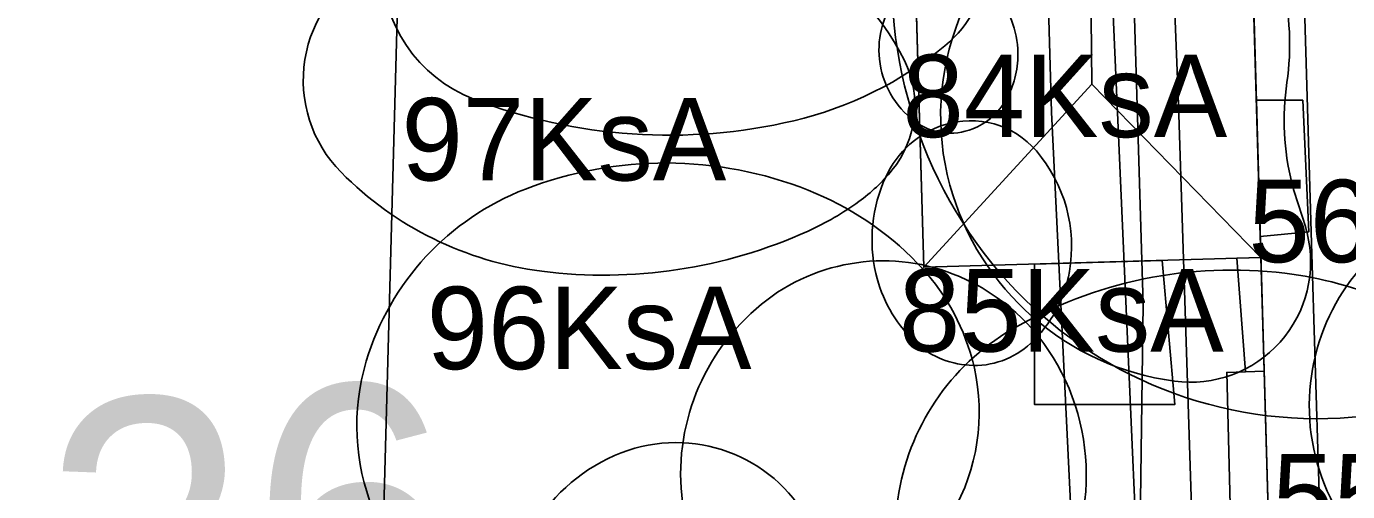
# Model space of a CAD drawing. Extents: x 738423 to 738903, y 6589762 to 6590172.
# Drawn here: x 738736.84 to 738760.87, y 6589904.32 to 6589912.78 of the extents above; entities that cross this region are included whole.
import ezdxf

# ---------------------------------------------------------------- set-up
doc = ezdxf.new("R2010")
doc.units = 0
for name, color, linetype in [('_1927_hoonestus', 7, 'Continuous'), ('_1927_katuse_kalded', 7, 'Continuous'), ('_1927_krundi_piir', 7, 'Continuous'), ('_1927_kvartali_nr_planžetil', 7, 'Continuous'), ('_ajalooline_kalmistu', 7, 'Continuous'), ('a_dendro_III_vk_puu', 7, 'Continuous'), ('a_dendro_IV_vk_puu', 7, 'Continuous'), ('a_dendro_puu_nr', 7, 'Continuous'), ('Default', 7, 'Continuous'), ('v_dp_jalak_liikumine', 7, 'Continuous'), ('v_olol_kitsendus_tehnov', 7, 'Continuous'), ('v_olol_transp_jjt_jalg', 7, 'Continuous'), ('v_olol_transp_tee', 7, 'Continuous')]:
    doc.layers.add(name, color=color, linetype=linetype)

# ---------------------------------------------------------------- blocks, each defined once
blk = doc.blocks.new('_U488')
at = {"layer": 'Default'}
for centre, radius, start, end in [((-0.0006707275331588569, 0.0073739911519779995), 0.007631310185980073, 93.92795558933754, 158.4941838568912), ((-0.0006671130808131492, 0.00732135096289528), 0.007684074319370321, 32.88450289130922, 93.92795558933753), ((-0.0074440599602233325, 0.002939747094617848), 0.015754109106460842, 351.3357863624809, 32.8845028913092), ((0.006888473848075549, 0.00439545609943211), 0.015756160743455, 158.4941838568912, 202.13591953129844), ((-0.004129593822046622, 0.002434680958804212), 0.012401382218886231, 318.6631581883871, 351.3357863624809), ((0.0035928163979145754, 0.003054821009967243), 0.012198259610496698, 202.13591953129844, 232.24430458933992), ((0.00023539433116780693, -0.0014050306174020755), 0.006587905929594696, 273.26195820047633, 318.6631581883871), ((0.0002287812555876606, -0.0012889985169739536), 0.006704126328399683, 232.24430458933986, 273.26195820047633)]:
    blk.add_arc(centre, radius, start, end, dxfattribs=at)
blk = doc.blocks.new('_U506')
at = {"layer": 'Default'}
for centre, radius, start, end in [((-0.0016138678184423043, 0.006289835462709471), 0.007716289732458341, 86.31829193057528, 151.30931070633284), ((-0.0016648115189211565, 0.005498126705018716), 0.008509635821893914, 34.56599987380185, 86.3182919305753), ((-0.0077425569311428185, 0.001310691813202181), 0.015890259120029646, 357.31565392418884, 34.56599987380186), ((0.005236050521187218, 0.00254106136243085), 0.01552491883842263, 151.30931070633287, 195.82186779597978), ((-0.005901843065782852, 0.0012243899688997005), 0.014047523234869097, 325.0458822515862, 357.31565392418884), ((0.003189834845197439, 0.0019611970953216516), 0.013398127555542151, 195.82186779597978, 231.62212624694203), ((-0.0007108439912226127, -0.002404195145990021), 0.007714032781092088, 280.99557181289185, 325.0458822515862), ((-0.000623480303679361, -0.002853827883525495), 0.007255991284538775, 231.62212624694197, 280.99557181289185)]:
    blk.add_arc(centre, radius, start, end, dxfattribs=at)
blk = doc.blocks.new('_U507')
at = {"layer": 'Default'}
for centre, radius, start, end in [((0.0022359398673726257, 0.003019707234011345), 0.009530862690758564, 35.84665147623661, 109.64435277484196), ((0.002331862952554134, 0.0027509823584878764), 0.009816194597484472, 109.64435277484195, 176.69754633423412), ((0.0056890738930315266, 0.005514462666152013), 0.005270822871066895, 288.1678476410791, 35.846651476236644), ((-0.0030984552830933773, 0.0030643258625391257), 0.004376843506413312, 176.69754633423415, 288.31198269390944), ((0.004344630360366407, 0.009611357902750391), 0.009582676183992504, 265.9817138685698, 288.1678476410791), ((0.0030107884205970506, -0.009376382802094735), 0.009451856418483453, 85.98171386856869, 108.32281673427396), ((0.002905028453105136, -0.009057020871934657), 0.009115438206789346, 108.32281673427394, 114.27670833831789), ((-0.004576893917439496, 0.007531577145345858), 0.009082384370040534, 288.31198269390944, 294.27670833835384)]:
    blk.add_arc(centre, radius, start, end, dxfattribs=at)
blk = doc.blocks.new('_U508')
at = {"layer": 'Default'}
for centre, radius, start, end in [((-0.0036318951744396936, -0.0023381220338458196), 0.016520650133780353, 81.24880080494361, 131.5308812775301), ((-0.003578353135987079, -0.00199030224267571), 0.016168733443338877, 45.24796613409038, 81.24880080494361), ((-0.0045002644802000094, -0.001357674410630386), 0.015210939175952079, 131.53088127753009, 184.09120010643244), ((-0.002796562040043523, -0.0012017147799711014), 0.015058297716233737, 7.896067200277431, 45.24796613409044), ((-0.002746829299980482, -0.0011948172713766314), 0.01500808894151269, 327.04674772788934, 7.896067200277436), ((-0.0045406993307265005, -0.0013605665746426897), 0.015170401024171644, 184.0912001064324, 237.08728459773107), ((-0.0037136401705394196, -0.0005680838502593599), 0.016160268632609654, 287.74292772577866, 327.0467477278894), ((-0.0038175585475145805, -0.00024330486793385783), 0.016501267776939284, 237.08728459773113, 287.74292772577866)]:
    blk.add_arc(centre, radius, start, end, dxfattribs=at)
blk = doc.blocks.new('_U534')
at = {"layer": 'Default'}
for centre, radius, start, end in [((0.00032315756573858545, -0.0007544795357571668), 0.0032282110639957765, 100.17419242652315, 147.53300546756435), ((0.0003344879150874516, -0.0008176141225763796), 0.0032923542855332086, 56.64981146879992, 100.17419242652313), ((0.0009196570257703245, 7.152245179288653e-05), 0.00222793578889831, 3.0724088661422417, 56.6498114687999), ((-0.0005577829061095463, -0.0001939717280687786), 0.002184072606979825, 147.53300546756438, 205.98706310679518), ((0.0007738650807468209, 6.36970533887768e-05), 0.0023739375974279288, 313.48710403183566, 3.072408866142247), ((-0.0003675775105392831, -0.00010125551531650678), 0.0023956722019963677, 205.98706310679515, 242.0445168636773), ((4.415659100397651e-05, 0.0008329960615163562), 0.0034342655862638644, 272.6785703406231, 313.48710403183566), ((5.0968495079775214e-05, 0.0006873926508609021), 0.003288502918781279, 242.04451686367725, 272.6785703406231)]:
    blk.add_arc(centre, radius, start, end, dxfattribs=at)
blk = doc.blocks.new('_U535')
at = {"layer": 'Default'}
for centre, radius, start, end in [((0.0012308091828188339, -0.0023203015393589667), 0.0049681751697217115, 107.30576081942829, 139.7935033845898), ((0.0013888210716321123, -0.0028274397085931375), 0.00549935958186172, 69.69332963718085, 107.30576081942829), ((0.00207351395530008, -0.000977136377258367), 0.003526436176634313, 22.215555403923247, 69.69332963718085), ((-0.00012164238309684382, -0.0011771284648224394), 0.0031973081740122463, 139.79350338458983, 180.60792843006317), ((0.0024281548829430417, -0.0008322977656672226), 0.003143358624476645, 314.79661835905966, 22.21555540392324), ((-0.00032605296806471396, -0.0011792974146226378), 0.0029928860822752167, 180.60792843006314, 227.37696867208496), ((0.000872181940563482, 0.0007347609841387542), 0.005351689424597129, 264.4529760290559, 314.7966183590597), ((0.0008057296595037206, 5.051439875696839e-05), 0.004664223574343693, 227.3769686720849, 264.4529760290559)]:
    blk.add_arc(centre, radius, start, end, dxfattribs=at)
blk = doc.blocks.new('_U536')
at = {"layer": 'Default'}
for centre, radius, start, end in [((0.0007962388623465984, 0.0021857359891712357), 0.007980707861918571, 43.48308980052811, 101.66907185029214), ((0.0007675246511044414, 0.002324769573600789), 0.007838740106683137, 101.66907185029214, 156.75288593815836), ((0.001496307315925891, 0.002849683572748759), 0.007015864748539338, 341.00823357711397, 43.48308980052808), ((-7.154895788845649e-06, 0.002657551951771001), 0.006995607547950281, 156.75288593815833, 215.3643296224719), ((0.0010639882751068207, 0.0029984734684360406), 0.007473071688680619, 303.56114930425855, 341.00823357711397), ((0.000350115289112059, 0.0029111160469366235), 0.00743371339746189, 215.36432962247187, 242.18631601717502), ((0.0006566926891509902, 0.0036124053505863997), 0.008209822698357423, 267.8931493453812, 303.5611493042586), ((0.0006519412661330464, 0.003483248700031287), 0.008080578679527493, 242.18631601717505, 267.8931493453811)]:
    blk.add_arc(centre, radius, start, end, dxfattribs=at)
blk = doc.blocks.new('_U545')
at = {"layer": 'Default'}
for centre, radius, start, end in [((0.0002801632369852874, 0.00467107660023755), 0.0062366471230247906, 100.70228308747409, 181.7054463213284), ((0.0003150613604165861, 0.004486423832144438), 0.006424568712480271, 25.48009298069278, 100.70228308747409), ((0.0011470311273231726, 0.004882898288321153), 0.005502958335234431, 302.96783248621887, 25.48009298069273), ((-0.00029692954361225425, 0.0046538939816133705), 0.005659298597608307, 181.70544632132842, 267.673322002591), ((-0.00011046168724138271, 0.006821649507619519), 0.007813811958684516, 287.35713986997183, 302.9678324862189), ((-0.00021003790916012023, 0.007140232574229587), 0.008147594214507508, 272.0715033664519, 287.3571398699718), ((-0.00020511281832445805, 0.006913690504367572), 0.007920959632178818, 267.673322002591, 269.8783066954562), ((-0.00020493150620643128, 0.006999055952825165), 0.008006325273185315, 269.8783066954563, 272.0715033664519)]:
    blk.add_arc(centre, radius, start, end, dxfattribs=at)
blk = doc.blocks.new('_U546')
at = {"layer": 'Default'}
for centre, radius, start, end in [((-0.0030265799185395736, 0.007981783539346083), 0.008193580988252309, 77.61053430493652, 154.49757135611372), ((-0.0033480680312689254, 0.00651828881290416), 0.009691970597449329, 25.43648688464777, 77.61053430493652), ((0.0020305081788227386, 0.0055694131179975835), 0.013796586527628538, 154.4975713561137, 211.75598620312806), ((-0.007353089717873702, 0.004613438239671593), 0.0141269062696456, 342.71622512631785, 25.43648688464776), ((-0.004697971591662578, 0.0037872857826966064), 0.01134622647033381, 318.4501417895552, 342.71622512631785), ((-0.0007812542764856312, 0.003829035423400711), 0.010489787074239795, 211.75598620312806, 247.08044385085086), ((-0.0022428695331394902, 0.0016113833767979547), 0.008065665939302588, 289.57933458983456, 318.45014178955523), ((-0.002003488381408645, 0.0009383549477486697), 0.007351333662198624, 247.0804438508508, 289.57933458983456)]:
    blk.add_arc(centre, radius, start, end, dxfattribs=at)
blk = doc.blocks.new('_U547')
at = {"layer": 'Default'}
for centre, radius, start, end in [((0.002327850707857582, 0.012856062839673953), 0.00476674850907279, 31.366537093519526, 138.98058165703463), ((0.008125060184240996, 0.007813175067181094), 0.01245039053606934, 138.98058165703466, 177.14331812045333), ((-0.008809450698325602, 0.006066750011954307), 0.017810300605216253, 342.01160273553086, 31.366537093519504), ((0.013719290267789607, 0.007534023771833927), 0.01805158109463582, 177.14331812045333, 208.64988950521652), ((4.1620773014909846e-05, 0.003192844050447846), 0.008504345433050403, 300.2461724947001, 342.01160273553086), ((0.007130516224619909, 0.00393426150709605), 0.010543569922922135, 208.6498895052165, 220.25108899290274), ((0.003951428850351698, 0.0012428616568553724), 0.006378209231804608, 220.2510889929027, 235.18367580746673), ((0.002443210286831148, -0.0009258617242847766), 0.003736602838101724, 235.18367580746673, 300.24617249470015)]:
    blk.add_arc(centre, radius, start, end, dxfattribs=at)
blk = doc.blocks.new('_U548')
at = {"layer": 'Default'}
for centre, radius, start, end in [((-0.0007984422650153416, 0.008774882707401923), 0.005225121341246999, 93.51041350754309, 163.3720066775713), ((-0.000795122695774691, 0.008720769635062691), 0.005279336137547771, 28.121308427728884, 93.51041350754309), ((-0.013553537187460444, 0.0019023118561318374), 0.019745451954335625, 355.6838438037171, 28.121308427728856), ((0.01321181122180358, 0.00459079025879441), 0.01984681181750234, 163.37200667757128, 197.54256395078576), ((-0.007684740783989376, 0.0014593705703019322), 0.013859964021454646, 326.657813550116, 355.6838438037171), ((0.0071611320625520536, 0.002678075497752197), 0.013501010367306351, 197.54256395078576, 223.80796263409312), ((0.0005087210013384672, -0.003931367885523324), 0.004052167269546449, 271.43577756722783, 326.6578135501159), ((0.0005031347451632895, -0.0037084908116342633), 0.004275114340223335, 223.80796263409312, 271.43577756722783)]:
    blk.add_arc(centre, radius, start, end, dxfattribs=at)

msp = doc.modelspace()

# ---------------------------------------------------------------- linework, layer by layer
at = {"layer": '_1927_hoonestus'}
for points in [[(738742.9119832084, 6589937.579054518), (738755.8497666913, 6589937.077773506), (738756.8029906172, 6589938.057600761), (738759.4850923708, 6589935.448320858), (738758.5480158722, 6589934.54201058), (738758.7178108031, 6589928.6132055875), (738760.266555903, 6589928.657560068), (738760.3706463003, 6589925.022989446), (738758.8231255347, 6589924.935884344), (738759.2916158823, 6589908.577398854), (738753.1586620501, 6589908.401757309), (738752.9623780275, 6589915.255493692), (738743.4516070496, 6589914.9831149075)], [(738759.2096281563, 6589911.440200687), (738760.0526017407, 6589911.440200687), (738760.1658016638, 6589909.046339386), (738759.2805882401, 6589908.96245593)], [(738755.1731812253, 6589908.459451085), (738755.1731812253, 6589905.904779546), (738757.7278527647, 6589905.904779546), (738757.4944519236, 6589908.525929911)], [(738759.0106733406, 6589906.498506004), (738758.8565014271, 6589908.5649376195), (738759.2916158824, 6589908.577398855), (738759.3508742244, 6589906.508249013)], [(738759.2251257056, 6589884.56227271), (738759.9817993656, 6589884.477955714), (738759.3508742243, 6589906.508249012), (738758.670472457, 6589906.488762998)]]:
    msp.add_lwpolyline(points, close=True, dxfattribs=at)
at = {"layer": '_1927_katuse_kalded'}
for points in [[(738756.2169037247, 6589911.730970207), (738756.1787003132, 6589915.382694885), (738752.9616277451, 6589915.281691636), (738753.1586620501, 6589908.401757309)], [(738759.2916158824, 6589908.577398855), (738756.2169037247, 6589911.730970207), (738756.1787003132, 6589915.382694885), (738759.0940977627, 6589915.474226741)], [(738756.2169037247, 6589911.730970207), (738753.1586620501, 6589908.401757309), (738759.2916158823, 6589908.577398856)]]:
    msp.add_lwpolyline(points, close=True, dxfattribs=at)
at = {"layer": '_1927_krundi_piir'}
msp.add_line((738759.9817993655, 6589884.477955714), (738758.4783109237, 6589936.975929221), dxfattribs=at)
at = {"layer": '_ajalooline_kalmistu'}
msp.add_lwpolyline([(738700.480405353, 6589884.053901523), (738711.8557000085, 6589939.5353000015), (738713.3969999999, 6589939.458000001), (738744.2612679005, 6589937.910991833), (738742.6678676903, 6589879.490577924)], close=True, dxfattribs=at)
at = {"layer": 'v_dp_jalak_liikumine'}
msp.add_lwpolyline([(738753.7352778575, 6590011.485218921), (738754.5485713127, 6589968.543440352), (738755.4664630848, 6589938.81512126), (738757.0489483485, 6589902.976712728), (738757.749514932, 6589889.633197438), (738760.3964895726, 6589885.01045508), (738760.6563499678, 6589876.988192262), (738761.0572489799, 6589862.973393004), (738761.3980093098, 6589851.105365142), (738761.7912117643, 6589844.0801351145)], dxfattribs=at)
at = {"layer": 'v_olol_kitsendus_tehnov'}
msp.add_lwpolyline([(738756.9105825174, 6589889.870097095), (738757.1525901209, 6589907.731297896), (738756.2368626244, 6589937.997240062), (738756.2034751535, 6589939.167527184)], dxfattribs=at)
at = {"layer": 'v_olol_transp_jjt_jalg'}
for points in [[(738753.3980000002, 6589984.476), (738754.3250000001, 6589953.163999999), (738755.04, 6589926.637), (738755.4860000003, 6589911.220000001), (738756.5250000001, 6589889.759999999), (738757.82206961, 6589886.935068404), (738757.3703897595, 6589885.530282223), (738754.0880000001, 6589882.902000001), (738752.2950952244, 6589882.167957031), (738745.265557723, 6589881.245987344), (738738.6560000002, 6589881.396000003), (738727.6409999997, 6589881.646000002), (738723.8518062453, 6589881.6181833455), (738723.8688999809, 6589879.598070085), (738727.889, 6589879.6620000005), (738739.6499999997, 6589879.9520000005), (738745.5079999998, 6589880.3), (738753.9679999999, 6589881.731000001), (738758.1444489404, 6589884.291527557), (738759.843, 6589884.707999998), (738760.6230000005, 6589848.891)], [(738762.2380000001, 6589844.465999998), (738761.5959999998, 6589867.022999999), (738760.9699535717, 6589884.81262032), (738760.8657554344, 6589887.773495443), (738759.372430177, 6589888.584165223), (738758.4950000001, 6589889.556), (738757.792, 6589911.368000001), (738757.1080000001, 6589928.520999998), (738756.3560000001, 6589953.211999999), (738755.3990000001, 6589984.343999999)]]:
    msp.add_lwpolyline(points, dxfattribs=at)
at = {"layer": 'v_olol_transp_tee'}
msp.add_lwpolyline([(738757.0262586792, 6590012.291021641), (738763.0496415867, 6590013.8166144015), (738763.91, 6589983.1489999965), (738764.929, 6589952.457999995), (738765.4810000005, 6589931.862999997), (738766.1660000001, 6589909.860999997), (738766.7020000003, 6589890.6209999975), (738767.8570000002, 6589856.707999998), (738768.121, 6589848.193999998), (738768.8037483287, 6589822.631606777), (738762.8293167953, 6589823.607741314), (738762.2380000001, 6589844.465999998), (738761.5959999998, 6589867.022999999), (738760.8119999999, 6589889.301), (738760.2139999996, 6589908.838999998), (738759.598, 6589929.524999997), (738758.8590000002, 6589952.364999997), (738757.8280000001, 6589984.569999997), (738757.361, 6590000.716999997)], close=True, dxfattribs=at)

# ---------------------------------------------------------------- block references
at = {"layer": 'a_dendro_III_vk_puu', "xscale": 500.0000000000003, "yscale": 500.0000000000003, "rotation": 85.69234851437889}
for name, p in [('_U508', (738759.809310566, 6589915.545442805)), ('_U548', (738750.316, 6589913.966999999)), ('_U507', (738759.6533105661, 6589909.927442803)), ('_U547', (738750.577, 6589910.16)), ('_U546', (738751.036, 6589906.727000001)), ('_U488', (738767.689310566, 6589905.933442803)), ('_U536', (738753.787310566, 6589904.156442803)), ('_U506', (738759.7073105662, 6589904.216442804)), ('_U545', (738751.0429999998, 6589901.704))]:
    msp.add_blockref(name, p, dxfattribs=at)
at = {"layer": 'a_dendro_IV_vk_puu', "xscale": 500.0000000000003, "yscale": 500.0000000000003, "rotation": 85.69234851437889}
for name, p in [('_U534', (738753.5703105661, 6589912.218442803)), ('_U535', (738753.5063105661, 6589908.316442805))]:
    msp.add_blockref(name, p, dxfattribs=at)

# ---------------------------------------------------------------- texts
at = {"layer": '_1927_kvartali_nr_planžetil'}
msp.add_text('26', height=4.999999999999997, rotation=3.560863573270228, dxfattribs=at).set_placement((738737.3695128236, 6589900.908596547))
at = {"layer": 'a_dendro_puu_nr'}
for s, p in [('84KsA', (738752.7710956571, 6589910.768420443)), ('97KsA', (738743.6589151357, 6589909.979455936)), ('56Va', (738759.0660247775, 6589908.491873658)), ('85KsA', (738752.7070956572, 6589906.866420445)), ('96KsA', (738744.1179151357, 6589906.546455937)), ('55Va', (738759.5015220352, 6589903.505493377))]:
    msp.add_text(s, height=1.5, dxfattribs=at).set_placement(p)

doc.saveas('drawing.dxf')
